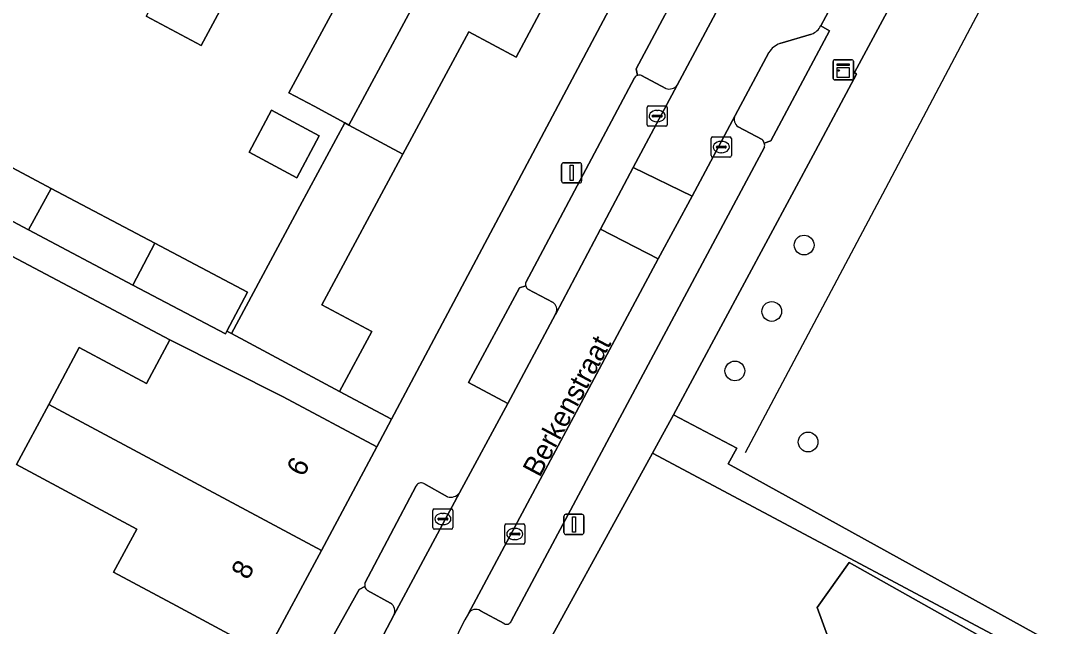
# Model space of a CAD drawing. Extents: x 159262 to 160143, y 383399 to 384319.
# Drawn here: x 159886 to 159937.9, y 383786.4 to 383816.3 of the extents above; entities that cross this region are included whole.
import ezdxf

# ---------------------------------------------------------------- set-up
doc = ezdxf.new("R2010")
doc.units = 0
for name, color, linetype in [('IMGEO_Boom', 7, 'Continuous'), ('IMGEO_Erf', 7, 'Continuous'), ('IMGEO_Groenvoorziening', 7, 'Continuous'), ('IMGEO_Hek', 7, 'Continuous'), ('IMGEO_Kast', 7, 'Continuous'), ('IMGEO_Kolk', 7, 'Continuous'), ('IMGEO_Lichtmast', 7, 'Continuous'), ('IMGEO_Openbare_ruimte_label', 7, 'Continuous'), ('IMGEO_Pand', 7, 'Continuous'), ('IMGEO_Pand_nummerreeks', 7, 'Continuous'), ('IMGEO_Parkeervlak_open', 7, 'Continuous'), ('IMGEO_Rijbaan_lokaal_open', 7, 'Continuous'), ('IMGEO_Voetpad_open', 7, 'Continuous')]:
    doc.layers.add(name, color=color, linetype=linetype)

msp = doc.modelspace()

# ---------------------------------------------------------------- linework, layer by layer
at = {"layer": 'IMGEO_Boom'}
for centre in [(159924.757, 383805.236), (159923.156, 383801.949), (159921.329, 383799.004), (159924.954, 383795.489)]:
    msp.add_circle(centre, 0.489, dxfattribs=at)
at = {"layer": 'IMGEO_Erf'}
for points in [[(159880.248, 383830.787), (159871.294, 383814.131), (159871.22, 383814), (159872.648, 383813.235), (159873.74, 383815.302), (159877.491, 383813.32), (159881.244, 383811.337), (159880.155, 383809.27), (159883.497, 383807.504), (159884.605, 383809.561), (159887.499, 383808.032), (159892.629, 383805.322), (159897.21, 383802.901), (159896.192, 383800.973), (159896.421, 383800.852), (159899.805, 383807.154), (159902.022, 383811.283), (159900.5, 383812.101), (159899.258, 383812.769), (159902.516, 383818.828)], [(159898.165, 383821.167), (159894.908, 383815.108), (159892.192, 383816.567)], [(159929.096, 383817.206), (159927.253, 383813.776), (159927.355, 383813.697), (159925.318, 383809.9), (159918.288, 383796.839), (159921.424, 383795.176), (159920.998, 383794.406), (159939.84, 383784), (159947.801, 383772.899), (159959.658, 383751.286)], [(159939.048, 383783.321), (159917.255, 383794.936), (159910.672, 383782.967)], [(159925.966, 383785.762), (159925.408, 383787.293), (159926.986, 383789.521), (159934.642, 383785.215)]]:
    msp.add_lwpolyline(points, dxfattribs=at)
for points in [[(159917.055, 383820.574), (159914.461, 383821.96), (159910.498, 383814.534), (159908.155, 383815.782), (159904.902, 383809.733), (159900.891, 383802.274), (159903.358, 383800.95), (159901.765, 383797.983), (159904.335, 383796.618)], [(159885.77, 383794.368), (159887.369, 383797.353), (159888.873, 383800.163), (159892.202, 383798.381), (159893.364, 383800.55), (159870.487, 383812.658), (159870.258, 383812.204), (159867.635, 383807.002), (159862.818, 383797.452), (159869.67, 383776.043), (159894.807, 383784.087), (159895.68, 383784.367), (159896.49, 383785.88), (159893.699, 383787.375), (159890.581, 383789.044), (159891.725, 383791.18)], [(159898.4, 383811.91), (159900.758, 383810.641), (159899.644, 383808.57), (159897.286, 383809.839)]]:
    msp.add_lwpolyline(points, close=True, dxfattribs=at)
at = {"layer": 'IMGEO_Groenvoorziening'}
for points in [[(159921.075, 383818.384), (159919.299, 383819.325), (159916.438, 383813.949), (159916.513, 383813.63)], [(159918.477, 383813.146), (159920.767, 383817.458)], [(159922.787, 383810.284), (159923.116, 383810.395), (159926.013, 383815.836), (159925.576, 383816.083)], [(159925.128, 383815.679), (159923.55, 383815.211)], [(159923.014, 383814.764), (159921.342, 383811.65)], [(159916.703, 383813.622), (159917.913, 383812.979)], [(159921.493, 383811.089), (159922.674, 383810.461)], [(159910.978, 383803.211), (159910.673, 383803.116), (159908.15, 383798.439), (159910.095, 383797.392), (159912.456, 383801.82)], [(159912.328, 383802.396), (159911.087, 383803.053)], [(159912.456, 383801.82), (159912.481, 383801.867)], [(159903.017, 383788.33), (159902.735, 383788.184), (159900.338, 383783.914), (159902.971, 383782.516)], [(159904.285, 383787.51), (159903.155, 383788.134)], [(159903.467, 383785.043), (159904.455, 383786.925)]]:
    msp.add_lwpolyline(points, dxfattribs=at)
for centre, radius, start, end in [((159924.82, 383816.471), 0.85, 291.2624, 332.825), ((159923.971, 383814.162), 1.13, 111.8425, 147.8107), ((159916.596, 383813.352), 0.29, 68.4525, 106.7255), ((159918.073, 383813.473), 0.519, 251.9962, 320.9918), ((159921.725, 383811.452), 0.431, 152.6824, 237.4473), ((159922.398, 383810.16), 0.408, 17.6561, 47.4537), ((159911.272, 383803.297), 0.307, 196.3691, 232.8324), ((159912.094, 383802.042), 0.425, 335.7451, 56.5173), ((159903.332, 383788.405), 0.324, 193.4044, 236.8929), ((159904.049, 383787.124), 0.453, 333.895, 58.5126)]:
    msp.add_arc(centre, radius, start, end, dxfattribs=at)
at = {"layer": 'IMGEO_Hek'}
for points in [[(159938.896, 383827.139), (159932.975, 383815.963)], [(159932.975, 383815.963), (159928.778, 383808.042)], [(159928.778, 383808.042), (159921.843, 383794.954)]]:
    msp.add_lwpolyline(points, dxfattribs=at)
at = {"layer": 'IMGEO_Kast'}
for p, q in [((159926.193, 383813.484), (159926.193, 383814.325)), ((159926.193, 383814.325), (159926.193, 383813.484)), ((159926.268, 383814.409), (159927.109, 383814.409)), ((159927.109, 383814.409), (159926.268, 383814.409)), ((159927.193, 383814.334), (159927.193, 383813.493)), ((159927.193, 383813.493), (159927.193, 383814.334)), ((159927.118, 383813.409), (159926.277, 383813.409)), ((159926.277, 383813.409), (159927.118, 383813.409))]:
    msp.add_line(p, q, dxfattribs=at)
for points in [[(159926.388, 383814.199), (159926.988, 383814.199), (159926.988, 383814.114), (159926.388, 383814.114), (159926.388, 383814.199)], [(159926.388, 383814.024), (159926.988, 383814.024), (159926.988, 383813.535), (159926.388, 383813.535), (159926.388, 383814.024)]]:
    msp.add_lwpolyline(points, dxfattribs=at)
msp.add_circle((159926.472, 383813.873), 0.0377, dxfattribs=at)
for centre, start, end in [((159926.271, 383814.331), 92.4484, 184.2845), ((159926.271, 383814.331), 92.4484, 184.2845), ((159927.115, 383814.331), 2.4484, 94.2845), ((159927.115, 383814.331), 2.4484, 94.2845), ((159926.271, 383813.487), 182.4484, 274.2845), ((159926.271, 383813.487), 182.4484, 274.2845), ((159927.115, 383813.487), 272.4484, 4.2845), ((159927.115, 383813.487), 272.4484, 4.2845)]:
    msp.add_arc(centre, 0.0779, start, end, dxfattribs=at)
at = {"layer": 'IMGEO_Kolk'}
for p, q in [((159916.983, 383811.192), (159916.983, 383812.044)), ((159917.058, 383812.118), (159917.91, 383812.118)), ((159917.471, 383811.898), (159917.496, 383811.898)), ((159917.984, 383812.044), (159917.984, 383811.192)), ((159917.242, 383811.612), (159917.242, 383811.624)), ((159917.68, 383811.575), (159917.282, 383811.575)), ((159917.285, 383811.661), (159917.683, 383811.661)), ((159917.494, 383811.338), (159917.469, 383811.338)), ((159917.726, 383811.624), (159917.726, 383811.612)), ((159917.91, 383811.118), (159917.058, 383811.118)), ((159920.155, 383809.66), (159920.155, 383810.512)), ((159920.23, 383810.586), (159921.082, 383810.586)), ((159920.457, 383810.129), (159920.855, 383810.129)), ((159920.643, 383810.366), (159920.668, 383810.366)), ((159921.156, 383810.512), (159921.156, 383809.66)), ((159920.414, 383810.08), (159920.414, 383810.092)), ((159920.852, 383810.043), (159920.454, 383810.043)), ((159920.666, 383809.806), (159920.641, 383809.806)), ((159920.898, 383810.092), (159920.898, 383810.08)), ((159921.082, 383809.586), (159920.23, 383809.586)), ((159906.377, 383791.252), (159906.377, 383792.104)), ((159906.452, 383792.178), (159907.304, 383792.178)), ((159907.378, 383792.104), (159907.378, 383791.252)), ((159906.636, 383791.672), (159906.636, 383791.684)), ((159907.074, 383791.635), (159906.676, 383791.635)), ((159906.679, 383791.721), (159907.077, 383791.721)), ((159906.865, 383791.958), (159906.89, 383791.958)), ((159907.12, 383791.684), (159907.12, 383791.672)), ((159907.304, 383791.178), (159906.452, 383791.178)), ((159906.888, 383791.398), (159906.863, 383791.398)), ((159909.936, 383790.51), (159909.936, 383791.362)), ((159910.011, 383791.436), (159910.863, 383791.436)), ((159910.195, 383790.93), (159910.195, 383790.942)), ((159910.238, 383790.979), (159910.636, 383790.979)), ((159910.424, 383791.216), (159910.449, 383791.216)), ((159910.679, 383790.942), (159910.679, 383790.93)), ((159910.937, 383791.362), (159910.937, 383790.51)), ((159910.863, 383790.436), (159910.011, 383790.436)), ((159910.633, 383790.893), (159910.235, 383790.893)), ((159910.447, 383790.656), (159910.422, 383790.656))]:
    msp.add_line(p, q, dxfattribs=at)
for points in [[(159916.983, 383811.192), (159916.983, 383812.044)], [(159917.058, 383812.118), (159917.91, 383812.118)], [(159917.984, 383812.044), (159917.984, 383811.192)], [(159917.91, 383811.118), (159917.058, 383811.118)], [(159920.155, 383809.66), (159920.155, 383810.512)], [(159920.23, 383810.586), (159921.082, 383810.586)], [(159921.156, 383810.512), (159921.156, 383809.66)], [(159921.082, 383809.586), (159920.23, 383809.586)], [(159906.377, 383791.252), (159906.377, 383792.104)], [(159906.452, 383792.178), (159907.304, 383792.178)], [(159907.378, 383792.104), (159907.378, 383791.252)], [(159907.304, 383791.178), (159906.452, 383791.178)], [(159909.936, 383790.51), (159909.936, 383791.362)], [(159910.011, 383791.436), (159910.863, 383791.436)], [(159910.937, 383791.362), (159910.937, 383790.51)], [(159910.863, 383790.436), (159910.011, 383790.436)]]:
    msp.add_lwpolyline(points, dxfattribs=at)
for centre, radius, start, end in [((159917.06, 383812.042), 0.0765, 91.552, 178.448), ((159917.06, 383812.042), 0.0765, 91.552, 178.448), ((159917.908, 383812.042), 0.0765, 1.552, 88.448), ((159917.908, 383812.042), 0.0765, 1.552, 88.448), ((159917.06, 383811.194), 0.0765, 181.552, 268.448), ((159917.06, 383811.194), 0.0765, 181.552, 268.448), ((159917.282, 383811.621), 0.0403, 85.8775, 175.7526), ((159917.279, 383811.611), 0.0366, 178.938, 274.7102), ((159917.683, 383811.618), 0.043, 264.8664, 352.4533), ((159917.687, 383811.623), 0.0386, 1.7309, 96.639), ((159917.908, 383811.194), 0.0765, 271.552, 358.448), ((159917.908, 383811.194), 0.0765, 271.552, 358.448), ((159920.232, 383810.51), 0.0765, 91.552, 178.448), ((159920.232, 383810.51), 0.0765, 91.552, 178.448), ((159920.454, 383810.089), 0.0403, 85.8775, 175.7526), ((159920.859, 383810.091), 0.0386, 1.7309, 96.639), ((159921.08, 383810.51), 0.0765, 1.552, 88.448), ((159921.08, 383810.51), 0.0765, 1.552, 88.448), ((159920.232, 383809.662), 0.0765, 181.552, 268.448), ((159920.232, 383809.662), 0.0765, 181.552, 268.448), ((159920.451, 383810.079), 0.0366, 178.938, 274.7102), ((159920.855, 383810.086), 0.043, 264.8664, 352.4533), ((159921.08, 383809.662), 0.0765, 271.552, 358.448), ((159921.08, 383809.662), 0.0765, 271.552, 358.448), ((159906.454, 383792.102), 0.0765, 91.552, 178.448), ((159906.454, 383792.102), 0.0765, 91.552, 178.448), ((159907.302, 383792.102), 0.0765, 1.552, 88.448), ((159907.302, 383792.102), 0.0765, 1.552, 88.448), ((159906.676, 383791.681), 0.0403, 85.8775, 175.7526), ((159906.673, 383791.671), 0.0366, 178.938, 274.7102), ((159907.077, 383791.678), 0.043, 264.8664, 352.4533), ((159907.081, 383791.683), 0.0386, 1.7309, 96.639), ((159906.454, 383791.254), 0.0765, 181.552, 268.448), ((159906.454, 383791.254), 0.0765, 181.552, 268.448), ((159907.302, 383791.254), 0.0765, 271.552, 358.448), ((159907.302, 383791.254), 0.0765, 271.552, 358.448), ((159910.013, 383791.36), 0.0765, 91.552, 178.448), ((159910.013, 383791.36), 0.0765, 91.552, 178.448), ((159910.235, 383790.939), 0.0403, 85.8775, 175.7526), ((159910.64, 383790.941), 0.0386, 1.7309, 96.639), ((159910.861, 383791.36), 0.0765, 1.552, 88.448), ((159910.861, 383791.36), 0.0765, 1.552, 88.448), ((159910.013, 383790.512), 0.0765, 181.552, 268.448), ((159910.013, 383790.512), 0.0765, 181.552, 268.448), ((159910.232, 383790.929), 0.0366, 178.938, 274.7102), ((159910.636, 383790.936), 0.043, 264.8664, 352.4533), ((159910.861, 383790.512), 0.0765, 271.552, 358.448), ((159910.861, 383790.512), 0.0765, 271.552, 358.448)]:
    msp.add_arc(centre, radius, start, end, dxfattribs=at)
for centre, major_axis, ratio, start_param, end_param in [((159917.47, 383811.618), (-0.387, 0.002), 0.722429, 4.712389, 7.853982), ((159917.495, 383811.618), (-0.39, 0.002), 0.717154, 1.570796, 4.712389), ((159920.642, 383810.086), (-0.387, 0.002), 0.722429, 4.712389, 7.853982), ((159920.667, 383810.086), (-0.39, 0.002), 0.717154, 1.570796, 4.712389), ((159906.864, 383791.678), (-0.387, 0.002), 0.722429, 4.712389, 7.853982), ((159906.889, 383791.678), (-0.39, 0.002), 0.717154, 1.570796, 4.712389), ((159910.423, 383790.936), (-0.387, 0.002), 0.722429, 4.712389, 7.853982), ((159910.448, 383790.936), (-0.39, 0.002), 0.717154, 1.570796, 4.712389)]:
    msp.add_ellipse(centre, major_axis=major_axis, ratio=ratio, start_param=start_param, end_param=end_param, dxfattribs=at)
at = {"layer": 'IMGEO_Lichtmast'}
for p, q in [((159912.755, 383808.408), (159912.755, 383809.208)), ((159912.755, 383809.208), (159912.755, 383808.408)), ((159912.855, 383809.308), (159913.645, 383809.308)), ((159913.645, 383809.308), (159912.855, 383809.308)), ((159913.745, 383809.208), (159913.745, 383808.408)), ((159913.745, 383808.408), (159913.745, 383809.208)), ((159913.645, 383808.308), (159912.855, 383808.308)), ((159912.855, 383808.308), (159913.645, 383808.308)), ((159912.865, 383791.01), (159912.865, 383791.81)), ((159912.865, 383791.81), (159912.865, 383791.01)), ((159912.965, 383791.91), (159913.755, 383791.91)), ((159913.755, 383791.91), (159912.965, 383791.91)), ((159913.855, 383791.81), (159913.855, 383791.01)), ((159913.855, 383791.01), (159913.855, 383791.81)), ((159913.755, 383790.91), (159912.965, 383790.91)), ((159912.965, 383790.91), (159913.755, 383790.91))]:
    msp.add_line(p, q, dxfattribs=at)
for points in [[(159913.175, 383809.183), (159913.325, 383809.183), (159913.325, 383808.433), (159913.175, 383808.433), (159913.175, 383809.183)], [(159913.285, 383791.785), (159913.435, 383791.785), (159913.435, 383791.035), (159913.285, 383791.035), (159913.285, 383791.785)]]:
    msp.add_lwpolyline(points, dxfattribs=at)
for centre, start, end in [((159912.855, 383809.208), 90, 180), ((159912.855, 383809.208), 90, 180), ((159913.645, 383809.208), 0, 90), ((159913.645, 383809.208), 360, 90), ((159912.855, 383808.408), 180, 270), ((159912.855, 383808.408), 180, 270), ((159913.645, 383808.408), 270, 0), ((159913.645, 383808.408), 270, 0), ((159912.965, 383791.81), 90, 180), ((159912.965, 383791.81), 90, 180), ((159913.755, 383791.81), 0, 90), ((159913.755, 383791.81), 360, 90), ((159912.965, 383791.01), 180, 270), ((159912.965, 383791.01), 180, 270), ((159913.755, 383791.01), 270, 0), ((159913.755, 383791.01), 270, 0)]:
    msp.add_arc(centre, 0.1, start, end, dxfattribs=at)
at = {"layer": 'IMGEO_Pand'}
for points in [[(159904.462, 383827.336), (159899.446, 383830.033), (159892.192, 383816.567), (159894.908, 383815.108), (159898.165, 383821.167), (159900.471, 383819.928)], [(159909.479, 383824.639), (159904.462, 383827.336), (159900.471, 383819.928), (159902.516, 383818.828), (159899.258, 383812.769), (159900.5, 383812.101), (159902.022, 383811.283), (159902.225, 383811.174)], [(159914.461, 383821.96), (159909.479, 383824.639), (159902.225, 383811.174), (159904.902, 383809.733), (159908.155, 383815.782), (159910.498, 383814.534)], [(159897.286, 383809.839), (159899.644, 383808.57), (159900.758, 383810.641), (159898.4, 383811.91)], [(159904.902, 383809.733), (159902.225, 383811.174), (159902.022, 383811.283), (159899.805, 383807.154), (159896.421, 383800.852), (159901.765, 383797.983), (159903.358, 383800.95), (159900.891, 383802.274)], [(159887.499, 383808.032), (159884.605, 383809.561), (159883.497, 383807.504), (159886.363, 383805.989)], [(159887.499, 383808.032), (159886.363, 383805.989), (159891.537, 383803.256), (159892.629, 383805.322)], [(159892.629, 383805.322), (159891.537, 383803.256), (159896.119, 383800.835), (159896.192, 383800.973), (159897.21, 383802.901)], [(159898.975, 383797.72), (159893.364, 383800.55), (159892.202, 383798.381), (159888.873, 383800.163), (159887.369, 383797.353), (159900.864, 383790.126), (159903.608, 383795.249)], [(159887.369, 383797.353), (159885.77, 383794.368), (159891.725, 383791.18), (159890.581, 383789.044), (159893.699, 383787.375), (159896.49, 383785.88), (159898.121, 383785.007), (159900.864, 383790.126)], [(159925.408, 383787.293), (159925.966, 383785.762), (159927.056, 383782.775), (159927.162, 383782.485), (159934.642, 383785.215), (159926.986, 383789.521)]]:
    msp.add_lwpolyline(points, close=True, dxfattribs=at)
at = {"layer": 'IMGEO_Parkeervlak_open'}
for points in [[(159916.356, 383813.518), (159910.976, 383803.387)], [(159917.913, 383812.979), (159916.703, 383813.622)], [(159912.481, 383801.867), (159914.678, 383806.016), (159916.294, 383809.074), (159918.477, 383813.146)], [(159921.342, 383811.65), (159919.212, 383807.655), (159917.54, 383804.561), (159908.14, 383787.005)], [(159922.674, 383810.461), (159921.493, 383811.089)], [(159910.257, 383786.623), (159922.795, 383810.075)], [(159911.087, 383803.053), (159912.328, 383802.396)], [(159905.556, 383793.324), (159903.022, 383788.501)], [(159907.11, 383792.778), (159905.929, 383793.43)], [(159904.455, 383786.925), (159907.699, 383792.974)], [(159903.155, 383788.134), (159904.285, 383787.51)], [(159908.736, 383787.138), (159909.905, 383786.501)]]:
    msp.add_lwpolyline(points, dxfattribs=at)
for centre, radius, start, end in [((159916.598, 383813.345), 0.297, 106.545, 144.4613), ((159916.596, 383813.352), 0.29, 68.4525, 106.7255), ((159918.073, 383813.473), 0.519, 251.9962, 320.9918), ((159921.725, 383811.452), 0.431, 152.6824, 237.4473), ((159922.398, 383810.16), 0.408, 17.6561, 47.4537), ((159922.408, 383810.165), 0.397, 346.9324, 17.4517), ((159911.268, 383803.302), 0.304, 163.8464, 197.4557), ((159911.272, 383803.297), 0.307, 196.3691, 232.8324), ((159912.094, 383802.042), 0.425, 335.7451, 56.5173), ((159905.793, 383793.199), 0.268, 59.5948, 152.1336), ((159907.26, 383793.309), 0.552, 254.2139, 322.5976), ((159903.331, 383788.406), 0.324, 162.9979, 193.6525), ((159903.332, 383788.405), 0.324, 193.4044, 236.8929), ((159904.049, 383787.124), 0.453, 333.895, 58.5126), ((159908.505, 383786.773), 0.432, 57.6467, 147.5127), ((159910.031, 383786.706), 0.241, 238.4843, 339.7474)]:
    msp.add_arc(centre, radius, start, end, dxfattribs=at)
at = {"layer": 'IMGEO_Rijbaan_lokaal_open'}
for points in [[(159925.576, 383816.083), (159926.828, 383818.404), (159929.845, 383823.994), (159932.902, 383829.761)], [(159920.767, 383817.458), (159918.477, 383813.146), (159916.294, 383809.074), (159919.212, 383807.655), (159921.342, 383811.65), (159923.014, 383814.764)], [(159923.55, 383815.211), (159925.128, 383815.679)], [(159917.54, 383804.561), (159914.678, 383806.016), (159912.481, 383801.867), (159912.456, 383801.82), (159910.095, 383797.392), (159907.699, 383792.974), (159904.455, 383786.925), (159903.467, 383785.043)], [(159908.14, 383787.005), (159917.54, 383804.561)]]:
    msp.add_lwpolyline(points, dxfattribs=at)
msp.add_lwpolyline([(159919.212, 383807.655), (159916.294, 383809.074), (159914.678, 383806.016), (159917.54, 383804.561)], close=True, dxfattribs=at)
for centre, radius, start, end in [((159924.82, 383816.471), 0.85, 291.2624, 332.825), ((159923.971, 383814.162), 1.13, 111.8425, 147.8107), ((159916.181, 383782.324), 9.304, 149.797, 184.6072)]:
    msp.add_arc(centre, radius, start, end, dxfattribs=at)
at = {"layer": 'IMGEO_Voetpad_open'}
for points in [[(159918.843, 383824.178), (159917.816, 383822.24), (159917.055, 383820.574), (159904.335, 383796.618), (159903.608, 383795.249), (159900.864, 383790.126), (159898.121, 383785.007), (159897.561, 383783.968), (159899.548, 383778.523), (159901.494, 383773.189), (159903.441, 383767.855), (159905.388, 383762.521), (159907.333, 383757.187), (159909.321, 383751.741)], [(159916.513, 383813.63), (159916.438, 383813.949), (159919.299, 383819.325), (159921.075, 383818.384)], [(159917.255, 383794.936), (159917.651, 383795.656), (159918.288, 383796.839), (159925.318, 383809.9), (159927.355, 383813.697), (159927.253, 383813.776), (159929.096, 383817.206), (159926.828, 383818.404), (159925.576, 383816.083), (159926.013, 383815.836), (159923.116, 383810.395), (159922.787, 383810.284)], [(159910.976, 383803.387), (159916.356, 383813.518)], [(159870.487, 383812.658), (159893.364, 383800.55), (159898.975, 383797.72), (159903.608, 383795.249), (159904.335, 383796.618), (159901.765, 383797.983), (159896.421, 383800.852), (159896.192, 383800.973), (159896.119, 383800.835), (159891.537, 383803.256), (159886.363, 383805.989), (159883.497, 383807.504)], [(159922.795, 383810.075), (159910.257, 383786.623)], [(159907.699, 383792.974), (159910.095, 383797.392), (159908.15, 383798.439), (159910.673, 383803.116), (159910.978, 383803.211)], [(159959.658, 383751.286), (159947.801, 383772.899), (159939.84, 383784), (159920.998, 383794.406), (159921.424, 383795.176), (159918.288, 383796.839), (159917.651, 383795.656), (159917.255, 383794.936), (159939.048, 383783.321), (159944.381, 383776.132), (159946.703, 383772.634), (159952.563, 383761.994), (159955.275, 383756.876), (159957.705, 383752.292)], [(159932.519, 383716.477), (159932.821, 383716.335), (159935.975, 383707.683), (159937.58, 383708.929), (159932.965, 383721.791), (159928.262, 383734.749), (159926.33, 383740.072), (159924.342, 383745.518), (159922.768, 383749.83), (159922.396, 383750.851), (159920.449, 383756.185), (159918.502, 383761.519), (159916.554, 383766.852), (159914.607, 383772.187), (159912.66, 383777.521), (159910.672, 383782.967), (159917.255, 383794.936)], [(159903.022, 383788.501), (159905.556, 383793.324)], [(159905.929, 383793.43), (159907.11, 383792.778)], [(159902.971, 383782.516), (159900.338, 383783.914), (159902.735, 383788.184), (159903.017, 383788.33)], [(159909.905, 383786.501), (159908.736, 383787.138)]]:
    msp.add_lwpolyline(points, dxfattribs=at)
for centre, radius, start, end in [((159916.598, 383813.345), 0.297, 106.545, 144.4613), ((159922.408, 383810.165), 0.397, 346.9324, 17.4517), ((159911.268, 383803.302), 0.304, 163.8464, 197.4557), ((159905.793, 383793.199), 0.268, 59.5948, 152.1336), ((159907.26, 383793.309), 0.552, 254.2139, 322.5976), ((159903.331, 383788.406), 0.324, 162.9979, 193.6525), ((159916.181, 383782.324), 9.304, 149.797, 184.6072), ((159908.505, 383786.773), 0.432, 57.6467, 147.5127), ((159910.031, 383786.706), 0.241, 238.4843, 339.7474)]:
    msp.add_arc(centre, radius, start, end, dxfattribs=at)

# ---------------------------------------------------------------- texts
at = {"layer": 'IMGEO_Openbare_ruimte_label'}
msp.add_text('Berkenstraat', height=1, rotation=61.9477, dxfattribs=at).set_placement((159911.663, 383793.698))
at = {"layer": 'IMGEO_Pand_nummerreeks'}
for s, p in [('6', (159899.966, 383793.719)), ('8', (159897.228, 383788.62))]:
    msp.add_text(s, height=1, rotation=61.7534, dxfattribs=at).set_placement(p)

doc.saveas('drawing.dxf')
